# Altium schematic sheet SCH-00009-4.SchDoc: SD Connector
size A4
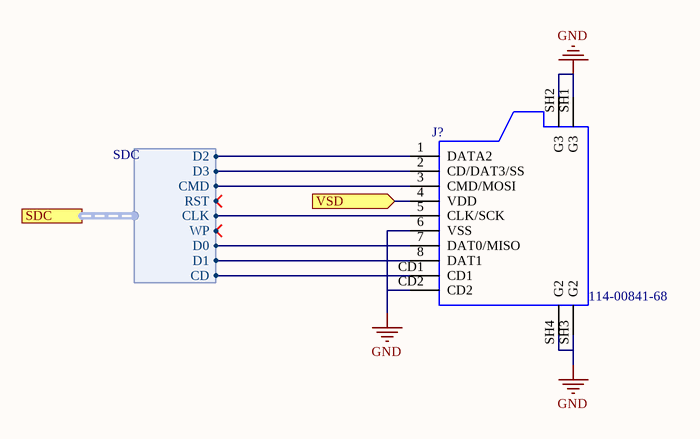
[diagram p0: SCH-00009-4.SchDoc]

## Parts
J?  114-00841-68  [AMPHENOL_114-00841-68]

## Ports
SDC (harness SDC), VSD (in)

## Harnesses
SDC: D0, D1, D2, D3, CMD, CLK, CD, WP, RST

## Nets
GND: J?.6(VSS) J?.CD2 J?.SH1(G3) J?.SH2(G3) J?.SH3(G2) J?.SH4(G2)
VSD: J?.4(VDD) ; port VSD
NetJ?_1: J?.1(DATA2) ; port SDC.D2
NetJ?_2: J?.2(CD/DAT3/SS) ; port SDC.D3
NetJ?_3: J?.3(CMD/MOSI) ; port SDC.CMD
NetJ?_5: J?.5(CLK/SCK) ; port SDC.CLK
NetJ?_7: J?.7(DAT0/MISO) ; port SDC.D0
NetJ?_8: J?.8(DAT1) ; port SDC.D1
NetJ?_CD1: J?.CD1 ; port SDC.CD

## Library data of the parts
J? = J0011-A.1: CONN Micro SD; Manufacturer: Amphenol; Code Arduino: A5328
